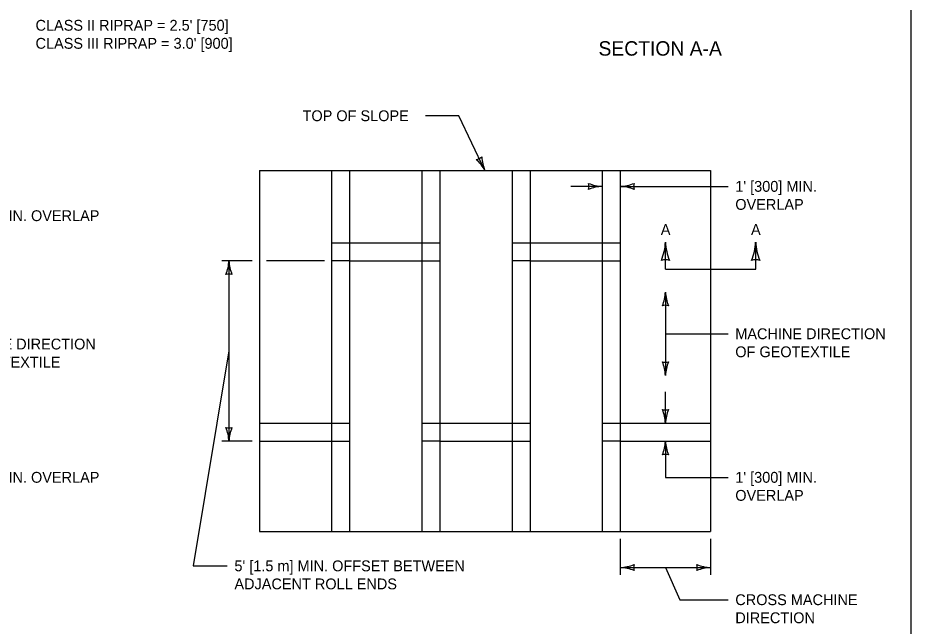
# Model space of a CAD drawing. Extents: x 49991.4 to 50021, y 49987.6 to 50011.4.
# Drawn here: x 50003.665 to 50008.615, y 50004.24 to 50007.611 of the extents above; entities that cross this region are included whole.
import ezdxf

# ---------------------------------------------------------------- set-up
doc = ezdxf.new("R2010")
doc.units = 0
for name, color, linetype in [('Level 1', 7, 'Continuous'), ('Level 2', 7, 'Continuous'), ('Level 3', 7, 'Continuous'), ('Level 4', 7, 'Continuous'), ('Level 6', 7, 'Continuous')]:
    doc.layers.add(name, color=color, linetype=linetype)

msp = doc.modelspace()

# ---------------------------------------------------------------- linework, layer by layer
at = {"layer": 'Level 1'}
for p, q in [((50005.0032, 50006.7648), (50005.0032, 50004.7648)), ((50005.0032, 50006.7648), (50007.5032, 50006.7648)), ((50005.5032, 50006.7648), (50005.5032, 50004.7648)), ((50006.0032, 50006.7648), (50006.0032, 50004.7648)), ((50006.5032, 50006.7648), (50006.5032, 50004.7648)), ((50007.0032, 50006.7648), (50007.0032, 50004.7648)), ((50007.5032, 50006.7648), (50007.5032, 50004.7648)), ((50005.5032, 50006.2648), (50006.0032, 50006.2648)), ((50006.5032, 50006.2648), (50007.0032, 50006.2648)), ((50005.0032, 50005.2648), (50005.5032, 50005.2648)), ((50006.0032, 50005.2648), (50006.5032, 50005.2648)), ((50007.0032, 50005.2648), (50007.5032, 50005.2648)), ((50005.0032, 50004.7648), (50007.5032, 50004.7648))]:
    msp.add_line(p, q, dxfattribs=at)
msp.add_lwpolyline([(50008.6146, 50011.2628), (50000.3356, 50011.2628), (50000.3356, 50000.0624), (50008.6146, 50000.0624)], close=True, dxfattribs=at)
at = {"layer": 'Level 3'}
for p, q in [((50006.1077, 50007.0683), (50005.9246, 50007.0683)), ((50006.2532, 50006.7648), (50006.1077, 50007.0683)), ((50006.9032, 50006.677), (50006.7298, 50006.677)), ((50007.0032, 50006.677), (50007.6003, 50006.677)), ((50004.9632, 50006.2648), (50004.7947, 50006.2648)), ((50004.8347, 50006.2648), (50004.8347, 50005.2648)), ((50005.3632, 50006.2648), (50005.0432, 50006.2648)), ((50007.2532, 50006.0915), (50007.2532, 50005.6292)), ((50007.2532, 50005.8603), (50007.6003, 50005.8603)), ((50004.8347, 50005.7648), (50004.6372, 50004.5743)), ((50007.2532, 50005.3648), (50007.2532, 50005.5382)), ((50004.9632, 50005.2648), (50004.7947, 50005.2648)), ((50007.2532, 50005.2648), (50007.2532, 50005.0648)), ((50007.2532, 50005.0648), (50007.6003, 50005.0648)), ((50007.0032, 50004.7248), (50007.0032, 50004.5248)), ((50007.5032, 50004.7248), (50007.5032, 50004.5248)), ((50004.6372, 50004.5743), (50004.825, 50004.5743)), ((50007.0032, 50004.5648), (50007.5032, 50004.5648)), ((50007.2532, 50004.5648), (50007.3335, 50004.3867)), ((50007.3335, 50004.3867), (50007.6003, 50004.3867))]:
    msp.add_line(p, q, dxfattribs=at)
for centre, radius, start, end in [((50006.1978, 50006.8804), 0.0548, 277.7511, 313.4735), ((50006.4575, 50006.8526), 0.2223, 183.0683, 203.2518), ((50006.0483, 50006.6538), 0.233, 28.4396, 47.6895), ((50006.9124, 50006.8991), 0.2223, 247.456, 267.6395), ((50006.775, 50006.677), 0.0548, 342.1388, 17.8612), ((50006.9917, 50006.9097), 0.233, 272.8273, 292.0772), ((50007.1314, 50006.677), 0.0548, 162.1388, 197.8612), ((50006.9147, 50006.4443), 0.233, 92.8273, 112.0772), ((50006.9941, 50006.4548), 0.2223, 67.456, 87.6395), ((50006.957, 50006.3803), 0.2964, 337.456, 357.6395), ((50007.5635, 50006.3834), 0.3107, 182.8273, 202.0772), ((50007.457, 50006.3803), 0.2964, 337.456, 357.6395), ((50008.0635, 50006.3834), 0.3107, 182.8273, 202.0772), ((50004.6126, 50006.2739), 0.2223, 337.456, 357.6395), ((50005.0674, 50006.2763), 0.233, 182.8273, 202.0772), ((50007.2532, 50006.1971), 0.073, 72.1388, 107.8612), ((50007.7532, 50006.1971), 0.073, 72.1388, 107.8612), ((50004.8347, 50006.1366), 0.0548, 72.1388, 107.8612), ((50007.0311, 50006.1007), 0.2223, 337.456, 357.6395), ((50007.4859, 50006.103), 0.233, 182.8273, 202.0772), ((50007.2532, 50005.9633), 0.0548, 72.1388, 107.8612), ((50007.2532, 50005.7574), 0.0548, 252.1388, 287.8612), ((50007.0205, 50005.6177), 0.233, 2.8273, 22.0772), ((50007.4753, 50005.62), 0.2223, 157.456, 177.6395), ((50007.2532, 50005.493), 0.0548, 252.1388, 287.8612), ((50007.0205, 50005.3533), 0.233, 2.8273, 22.0772), ((50007.4753, 50005.3556), 0.2223, 157.456, 177.6395), ((50004.8347, 50005.393), 0.0548, 252.1388, 287.8612), ((50004.602, 50005.2533), 0.233, 2.8273, 22.0772), ((50005.0568, 50005.2556), 0.2223, 157.456, 177.6395), ((50007.0311, 50005.2739), 0.2223, 337.456, 357.6395), ((50007.4859, 50005.2763), 0.233, 182.8273, 202.0772), ((50007.2532, 50005.1366), 0.0548, 72.1388, 107.8612), ((50006.9917, 50004.7975), 0.233, 272.8273, 292.0772), ((50006.9941, 50004.3427), 0.2223, 67.456, 87.6395), ((50007.1314, 50004.5648), 0.0548, 162.1388, 197.8612), ((50007.5124, 50004.7869), 0.2223, 247.456, 267.6395), ((50007.375, 50004.5648), 0.0548, 342.1388, 17.8612), ((50007.5147, 50004.3321), 0.233, 92.8273, 112.0772)]:
    msp.add_arc(centre, radius, start, end, dxfattribs=at)
at = {"layer": 'Level 4'}
for p, q in [((50005.4032, 50006.7648), (50005.4032, 50004.7648)), ((50005.9032, 50006.7648), (50005.9032, 50004.7648)), ((50006.4032, 50006.7648), (50006.4032, 50004.7648)), ((50006.9032, 50006.7648), (50006.9032, 50004.7648)), ((50005.4032, 50006.3648), (50006.0032, 50006.3648)), ((50006.4032, 50006.3648), (50007.0032, 50006.3648)), ((50005.5032, 50006.2648), (50005.4032, 50006.2648)), ((50006.5032, 50006.2648), (50006.4032, 50006.2648)), ((50005.0032, 50005.3648), (50005.5032, 50005.3648)), ((50005.9032, 50005.3648), (50006.5032, 50005.3648)), ((50006.9032, 50005.3648), (50007.5032, 50005.3648)), ((50006.0032, 50005.2648), (50005.9032, 50005.2648)), ((50007.0032, 50005.2648), (50006.9032, 50005.2648))]:
    msp.add_line(p, q, dxfattribs=at)
at = {"layer": 'Level 6'}
for p, q in [((50007.2532, 50006.2181), (50007.2532, 50006.3681)), ((50007.7532, 50006.2181), (50007.7532, 50006.3681)), ((50007.2532, 50006.2181), (50007.7532, 50006.2181))]:
    msp.add_line(p, q, dxfattribs=at)

# ---------------------------------------------------------------- texts
at = {"layer": 'Level 2'}
for s, height, p in [("CLASS II RIPRAP = 2.5' [750]", 0.06, (50003.763, 50007.5395)), ("CLASS III RIPRAP = 3.0' [900]", 0.06, (50003.763, 50007.4395)), ('SECTION A-A', 0.08, (50006.8824, 50007.4013)), ('TOP OF SLOPE', 0.06, (50005.2426, 50007.0383)), ("1' [300] MIN.", 0.06, (50007.6403, 50006.647)), ('OVERLAP', 0.06, (50007.6403, 50006.547)), ("1' [300] MIN. OVERLAP", 0.06, (50003.2633, 50006.4845)), ('A', 0.06, (50007.2275, 50006.4081)), ('A', 0.06, (50007.7275, 50006.4081)), ('MACHINE DIRECTION', 0.06, (50007.6403, 50005.8303)), ('MACHINE DIRECTION ', 0.06, (50003.2633, 50005.7732)), ('OF GEOTEXTILE', 0.06, (50007.6403, 50005.7303)), ('OF GEOTEXTILE', 0.06, (50003.2633, 50005.6732)), ("1' [300] MIN. OVERLAP", 0.06, (50003.2633, 50005.0348)), ("1' [300] MIN.", 0.06, (50007.6403, 50005.0348)), ('OVERLAP', 0.06, (50007.6403, 50004.9348)), ("5' [1.5 m] MIN. OFFSET BETWEEN", 0.06, (50004.865, 50004.5443)), ('ADJACENT ROLL ENDS', 0.06, (50004.865, 50004.4443)), ('CROSS MACHINE', 0.06, (50007.6403, 50004.3567)), ('DIRECTION', 0.06, (50007.6403, 50004.2567))]:
    msp.add_text(s, height=height, dxfattribs=at).set_placement(p)

doc.saveas('drawing.dxf')
